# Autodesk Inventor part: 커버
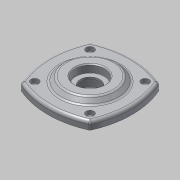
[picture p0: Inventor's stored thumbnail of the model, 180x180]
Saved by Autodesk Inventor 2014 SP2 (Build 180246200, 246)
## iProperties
Created: 2016-05
Part Number: 커버
Document SubType Name: Modeling
Designer: mduedu
Density: 2.71 g/cm^3
Material: 알루미늄 6061
Appearance: 알루미늄 - 평지
Author: mduedu
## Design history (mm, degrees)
sketch "스케치1"
  geometry: L1 (0, 0)-(-35.355, 35.355); L2 (0, 0)-(0, 43); L3 (0, 0)-(43, 0); C1 r 25 at (0, 0); A1 r 85.579 centre (0, -42.579) between (35.355, 35.355) and (-35.355, 35.355); A2 r 85.579 centre (42.579, 0) between (-35.355, 35.355) and (-35.355, -35.355); A3 r 85.579 centre (0, 42.579) between (-35.355, -35.355) and (35.355, -35.355); A4 r 85.579 centre (-42.579, 0) between (35.355, -35.355) and (35.355, 35.355); 1 further point
  constraints: 10 point on circle, 6 end point, 5 centre point, 2 horizontal alignment, 2 vertical alignment, 1 coincident, 1 equal radius, 2 other
  dimensions: "d28" = 86 dimension on A4 A2; "d30" = 50 diameter of C1; "d31" = 45 deg angle of L2 L1; "d32" = 100 distance of A3.end L1.end
extrude "돌출1" new body sketch "스케치1" distance "d0" = 8; taper "d1" = 0 deg
extrude "돌출2" join sketch "스케치1" distance "d2" = 12; taper "d3" = 0 deg
sketch "스케치2"
  geometry: C1 r 30 at (0, 0); 1 further point
  constraints: 1 centre point, 1 coincident
  dimensions: "d4" = 60 diameter of C1
extrude "돌출3" join sketch "스케치2" distance "d5" = 5; taper "d6" = -45 deg
sketch "스케치3"
  geometry: C1 r 1.621 at (-28.284, 28.284) reference; C2 r 1.621 at (28.284, 28.284) reference; C3 r 1.621 at (28.284, -28.284) reference; C4 r 1.621 at (-28.284, -28.284) reference; 1 further point
hole "구멍1" sketch "스케치3" at (28.284, 28.284), (-28.284, 28.284), (-28.284, -28.284), (28.284, -28.284) diameter "d7" = 4.5; stored, may be unused: countersink angle "d11" = 90 deg, drill point angle "d13" = 118 deg; dims "d8" = 6, "d9" = 8, "d10" = 4.4, "d12" = 8
fillet "모깎기1" dims "d14" = 3
sketch "스케치4"
  geometry: L1 (-23.757, 13)-(23.757, 13) reference; L2 (25, -12)-(-25, -12) reference; L3 (0, -12)-(0, 13); L4 (-20, -12)-(-20, 0); L5 (-20, 0)-(-15, 0); L6 (-15, 0)-(-15, 3); L7 (-15, 3)-(-10, 3); L8 (-10, 3)-(-10, 5); L9 (-10, 5)-(-15, 5); L10 (-15, 5)-(-15, 13); 1 further point
  constraints: 16 end point, 6 parallel, 2 midpoint, 2 point on line, 1 perpendicular
  dimensions: "d15" = 40 diameter of L4 L3; "d16" = 30 diameter of L10 L3; "d17" = 8 distance of L9.end L10.end; "d18" = 12 distance of L4.start L4.end; "d19" = 3 distance of L5.end L6.end; "d20" = 30 diameter of L6 L3; "d21" = 20 diameter of L8 L3
revolve "회전1" sketch "스케치4" stored, may be unused: angle "d22" = 90 deg
fillet "모깎기2" dims "d23" = 3
fillet "모깎기3" dims "d24" = 0.3
chamfer "모따기1" distance "d25" = 1; stored, may be unused: second distance "d26" = 2, angle "d27" = 45 deg
node "솔리드1"
node "참조2"
node "참조3"
node "참조4"
node "참조5"
